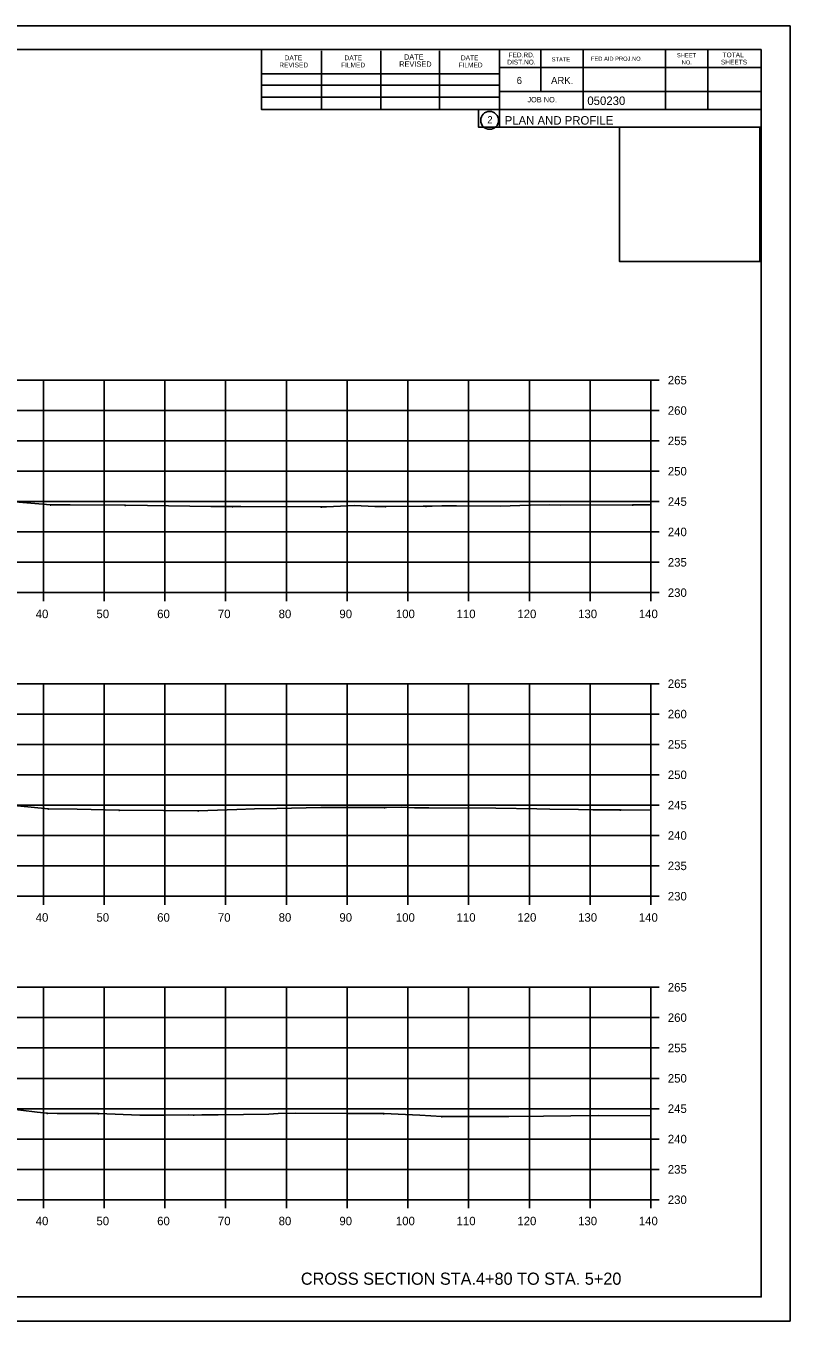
# Model space of a CAD drawing. Extents: x 1300404 to 1323571, y 234004 to 252077.
# Drawn here: x 1315754.4 to 1315880.2, y 241701.8 to 241915.1 of the extents above; entities that cross this region are included whole.
import ezdxf

# ---------------------------------------------------------------- set-up
doc = ezdxf.new("R2010")
doc.units = 0
for name, color, linetype in [('Default', 7, 'Continuous'), ('R_Axis', 7, 'Continuous'), ('R_Axis Annot', 7, 'Continuous'), ('R_Border', 7, 'Continuous'), ('R_Border Prem', 7, 'Continuous'), ('R_Draft', 7, 'Continuous'), ('R_Exist Surface', 7, 'Continuous'), ('R_Grid', 7, 'Continuous'), ('R_No Plot', 7, 'Continuous')]:
    doc.layers.add(name, color=color, linetype=linetype)

msp = doc.modelspace()

# ---------------------------------------------------------------- linework, layer by layer
at = {"layer": 'Default'}
for p, q in [((1315559.28, 241911.23), (1315875.46, 241911.23)), ((1315793.2, 241901.35), (1315793.2, 241911.23)), ((1315803.06, 241901.35), (1315803.06, 241911.03)), ((1315812.82, 241901.35), (1315812.82, 241911.03)), ((1315822.5, 241901.35), (1315822.5, 241911.03)), ((1315832.36, 241911.23), (1315832.36, 241898.43)), ((1315839.2, 241911.23), (1315839.2, 241904.29)), ((1315846.14, 241911.23), (1315846.14, 241901.35)), ((1315859.72, 241911.23), (1315859.72, 241901.35)), ((1315866.66, 241911.23), (1315866.66, 241901.35)), ((1315875.46, 241705.77), (1315875.46, 241911.23)), ((1315875.46, 241908.29), (1315832.36, 241908.29)), ((1315875.46, 241908.31), (1315875.46, 241908.31)), ((1315793.2, 241907.21), (1315832.36, 241907.21)), ((1315793.2, 241905.35), (1315832.36, 241905.35)), ((1315875.46, 241904.29), (1315832.36, 241904.29)), ((1315835.32, 241904.29), (1315875.46, 241904.29)), ((1315793.2, 241901.35), (1315793.2, 241903.41)), ((1315793.2, 241903.41), (1315832.36, 241903.41)), ((1315875.46, 241901.35), (1315793.2, 241901.35)), ((1315832.36, 241898.43), (1315875.46, 241898.43)), ((1315875.46, 241705.77), (1315559.28, 241705.77))]:
    msp.add_line(p, q, dxfattribs=at)
msp.add_circle((1315830.74, 241899.56), 1.47, dxfattribs=at)
at = {"layer": 'R_Axis'}
for p, q in [((1315857.28, 241821.77), (1315857.28, 241856.77)), ((1315858.68, 241856.77), (1315857.28, 241856.77)), ((1315858.68, 241851.77), (1315857.28, 241851.77)), ((1315858.68, 241846.77), (1315857.28, 241846.77)), ((1315858.68, 241841.77), (1315857.28, 241841.77)), ((1315858.68, 241836.77), (1315857.28, 241836.77)), ((1315858.68, 241831.77), (1315857.28, 241831.77)), ((1315858.68, 241826.77), (1315857.28, 241826.77)), ((1315577.28, 241821.77), (1315857.28, 241821.77)), ((1315757.28, 241820.37), (1315757.28, 241821.77)), ((1315767.28, 241820.37), (1315767.28, 241821.77)), ((1315777.28, 241820.37), (1315777.28, 241821.77)), ((1315787.28, 241820.37), (1315787.28, 241821.77)), ((1315797.28, 241820.37), (1315797.28, 241821.77)), ((1315807.28, 241820.37), (1315807.28, 241821.77)), ((1315817.28, 241820.37), (1315817.28, 241821.77)), ((1315827.28, 241820.37), (1315827.28, 241821.77)), ((1315837.28, 241820.37), (1315837.28, 241821.77)), ((1315847.28, 241820.37), (1315847.28, 241821.77)), ((1315857.28, 241820.37), (1315857.28, 241821.77)), ((1315858.68, 241821.77), (1315857.28, 241821.77)), ((1315857.28, 241771.77), (1315857.28, 241806.77)), ((1315858.68, 241806.77), (1315857.28, 241806.77)), ((1315858.68, 241801.77), (1315857.28, 241801.77)), ((1315858.68, 241796.77), (1315857.28, 241796.77)), ((1315858.68, 241791.77), (1315857.28, 241791.77)), ((1315858.68, 241786.77), (1315857.28, 241786.77)), ((1315858.68, 241781.77), (1315857.28, 241781.77)), ((1315858.68, 241776.77), (1315857.28, 241776.77)), ((1315577.28, 241771.77), (1315857.28, 241771.77)), ((1315757.28, 241770.37), (1315757.28, 241771.77)), ((1315767.28, 241770.37), (1315767.28, 241771.77)), ((1315777.28, 241770.37), (1315777.28, 241771.77)), ((1315787.28, 241770.37), (1315787.28, 241771.77)), ((1315797.28, 241770.37), (1315797.28, 241771.77)), ((1315807.28, 241770.37), (1315807.28, 241771.77)), ((1315817.28, 241770.37), (1315817.28, 241771.77)), ((1315827.28, 241770.37), (1315827.28, 241771.77)), ((1315837.28, 241770.37), (1315837.28, 241771.77)), ((1315847.28, 241770.37), (1315847.28, 241771.77)), ((1315857.28, 241770.37), (1315857.28, 241771.77)), ((1315858.68, 241771.77), (1315857.28, 241771.77)), ((1315857.28, 241721.77), (1315857.28, 241756.77)), ((1315858.68, 241756.77), (1315857.28, 241756.77)), ((1315858.68, 241751.77), (1315857.28, 241751.77)), ((1315858.68, 241746.77), (1315857.28, 241746.77)), ((1315858.68, 241741.77), (1315857.28, 241741.77)), ((1315858.68, 241736.77), (1315857.28, 241736.77)), ((1315858.68, 241731.77), (1315857.28, 241731.77)), ((1315858.68, 241726.77), (1315857.28, 241726.77)), ((1315577.28, 241721.77), (1315857.28, 241721.77)), ((1315757.28, 241720.37), (1315757.28, 241721.77)), ((1315767.28, 241720.37), (1315767.28, 241721.77)), ((1315777.28, 241720.37), (1315777.28, 241721.77)), ((1315787.28, 241720.37), (1315787.28, 241721.77)), ((1315797.28, 241720.37), (1315797.28, 241721.77)), ((1315807.28, 241720.37), (1315807.28, 241721.77)), ((1315817.28, 241720.37), (1315817.28, 241721.77)), ((1315827.28, 241720.37), (1315827.28, 241721.77)), ((1315837.28, 241720.37), (1315837.28, 241721.77)), ((1315847.28, 241720.37), (1315847.28, 241721.77)), ((1315857.28, 241720.37), (1315857.28, 241721.77)), ((1315858.68, 241721.77), (1315857.28, 241721.77))]:
    msp.add_line(p, q, dxfattribs=at)
at = {"layer": 'R_Draft'}
for points in [[(1315758.47, 241836.3), (1315758.52, 241836.2), (1315758.42, 241836.2)], [(1315770.75, 241836.22), (1315770.8, 241836.12), (1315770.7, 241836.12)], [(1315788.41, 241836), (1315788.46, 241835.9), (1315788.36, 241835.9)], [(1315803.05, 241835.94), (1315803.1, 241835.84), (1315803, 241835.84)], [(1315813.63, 241836.01), (1315813.68, 241835.91), (1315813.58, 241835.91)], [(1315820.28, 241836.05), (1315820.33, 241835.95), (1315820.23, 241835.95)], [(1315837.35, 241836.21), (1315837.4, 241836.11), (1315837.3, 241836.11)], [(1315854.29, 241836.27), (1315854.34, 241836.17), (1315854.24, 241836.17)], [(1315758.08, 241786.22), (1315758.13, 241786.12), (1315758.03, 241786.12)], [(1315813.44, 241786.45), (1315813.49, 241786.35), (1315813.39, 241786.35)], [(1315769.75, 241786.01), (1315769.8, 241785.91), (1315769.7, 241785.91)], [(1315782.76, 241785.89), (1315782.81, 241785.79), (1315782.71, 241785.79)], [(1315852.28, 241786.03), (1315852.33, 241785.93), (1315852.23, 241785.93)], [(1315757.91, 241736.06), (1315757.96, 241735.96), (1315757.86, 241735.96)], [(1315766.34, 241736.01), (1315766.39, 241735.91), (1315766.29, 241735.91)], [(1315782.03, 241735.78), (1315782.08, 241735.68), (1315781.98, 241735.68)], [(1315813.32, 241736.02), (1315813.37, 241735.92), (1315813.27, 241735.92)], [(1315822.87, 241735.52), (1315822.92, 241735.42), (1315822.82, 241735.42)], [(1315833.85, 241735.56), (1315833.9, 241735.46), (1315833.8, 241735.46)]]:
    msp.add_lwpolyline(points, close=True, dxfattribs=at)
at = {"layer": 'R_Exist Surface'}
for points in [[(1315748.62, 241837.08), (1315756.55, 241836.38), (1315758.47, 241836.25), (1315759.64, 241836.25), (1315761.67, 241836.21), (1315770.75, 241836.17), (1315774.43, 241836.14), (1315784.82, 241835.98), (1315788.41, 241835.95), (1315789.78, 241835.96), (1315803.05, 241835.89), (1315803.46, 241835.89), (1315803.87, 241835.91), (1315808.52, 241836.1), (1315811.87, 241835.95), (1315813.63, 241835.96), (1315819.81, 241836), (1315820.28, 241836), (1315821.3, 241836.01), (1315822.85, 241836.06), (1315824.2, 241836.06), (1315824.34, 241836.07), (1315825.3, 241836.05), (1315832.5, 241835.99), (1315837.35, 241836.16), (1315840.52, 241836.22), (1315842.46, 241836.16), (1315854.29, 241836.22), (1315857.1, 241836.25), (1315857.28, 241836.24)], [(1315750.74, 241786.89), (1315758.08, 241786.17), (1315762.86, 241786.11), (1315769.75, 241785.96), (1315777.03, 241785.91), (1315782.76, 241785.84), (1315789.12, 241786.07), (1315792.06, 241786.16), (1315795.71, 241786.2), (1315802.93, 241786.36), (1315813.44, 241786.4), (1315813.79, 241786.39), (1315816.18, 241786.41), (1315818.35, 241786.35), (1315820.76, 241786.32), (1315831.76, 241786.26), (1315838.51, 241786.17), (1315840.67, 241786.13), (1315845.4, 241786.06), (1315847.75, 241786.02), (1315852.28, 241785.98), (1315857.28, 241785.94)], [(1315748.12, 241737.18), (1315756.27, 241736.19), (1315757.91, 241736.01), (1315759.53, 241735.97), (1315766.34, 241735.96), (1315773.16, 241735.73), (1315777.19, 241735.71), (1315781.09, 241735.75), (1315782.03, 241735.73), (1315783.37, 241735.78), (1315786.03, 241735.75), (1315794.41, 241735.88), (1315795.95, 241735.98), (1315798.8, 241736.03), (1315807.46, 241735.97), (1315813.32, 241735.97), (1315819.24, 241735.71), (1315822.87, 241735.47), (1315823.16, 241735.47), (1315833.85, 241735.51), (1315839.63, 241735.56), (1315848.6, 241735.63), (1315857.28, 241735.6)]]:
    msp.add_lwpolyline(points, dxfattribs=at)
at = {"layer": 'R_Grid'}
for p, q in [((1315577.28, 241856.77), (1315857.28, 241856.77)), ((1315757.28, 241821.77), (1315757.28, 241856.77)), ((1315767.28, 241821.77), (1315767.28, 241856.77)), ((1315777.28, 241821.77), (1315777.28, 241856.77)), ((1315787.28, 241821.77), (1315787.28, 241856.77)), ((1315797.28, 241821.77), (1315797.28, 241856.77)), ((1315807.28, 241821.77), (1315807.28, 241856.77)), ((1315817.28, 241821.77), (1315817.28, 241856.77)), ((1315827.28, 241821.77), (1315827.28, 241856.77)), ((1315837.28, 241821.77), (1315837.28, 241856.77)), ((1315847.28, 241821.77), (1315847.28, 241856.77)), ((1315857.28, 241821.77), (1315857.28, 241856.77)), ((1315577.28, 241851.77), (1315857.28, 241851.77)), ((1315577.28, 241846.77), (1315857.28, 241846.77)), ((1315577.28, 241841.77), (1315857.28, 241841.77)), ((1315577.28, 241836.77), (1315857.28, 241836.77)), ((1315577.28, 241831.77), (1315857.28, 241831.77)), ((1315577.28, 241826.77), (1315857.28, 241826.77)), ((1315577.28, 241821.77), (1315857.28, 241821.77)), ((1315577.28, 241806.77), (1315857.28, 241806.77)), ((1315757.28, 241771.77), (1315757.28, 241806.77)), ((1315767.28, 241771.77), (1315767.28, 241806.77)), ((1315777.28, 241771.77), (1315777.28, 241806.77)), ((1315787.28, 241771.77), (1315787.28, 241806.77)), ((1315797.28, 241771.77), (1315797.28, 241806.77)), ((1315807.28, 241771.77), (1315807.28, 241806.77)), ((1315817.28, 241771.77), (1315817.28, 241806.77)), ((1315827.28, 241771.77), (1315827.28, 241806.77)), ((1315837.28, 241771.77), (1315837.28, 241806.77)), ((1315847.28, 241771.77), (1315847.28, 241806.77)), ((1315857.28, 241771.77), (1315857.28, 241806.77)), ((1315577.28, 241801.77), (1315857.28, 241801.77)), ((1315577.28, 241796.77), (1315857.28, 241796.77)), ((1315577.28, 241791.77), (1315857.28, 241791.77)), ((1315577.28, 241786.77), (1315857.28, 241786.77)), ((1315577.28, 241781.77), (1315857.28, 241781.77)), ((1315577.28, 241776.77), (1315857.28, 241776.77)), ((1315577.28, 241771.77), (1315857.28, 241771.77)), ((1315577.28, 241756.77), (1315857.28, 241756.77)), ((1315757.28, 241721.77), (1315757.28, 241756.77)), ((1315767.28, 241721.77), (1315767.28, 241756.77)), ((1315777.28, 241721.77), (1315777.28, 241756.77)), ((1315787.28, 241721.77), (1315787.28, 241756.77)), ((1315797.28, 241721.77), (1315797.28, 241756.77)), ((1315807.28, 241721.77), (1315807.28, 241756.77)), ((1315817.28, 241721.77), (1315817.28, 241756.77)), ((1315827.28, 241721.77), (1315827.28, 241756.77)), ((1315837.28, 241721.77), (1315837.28, 241756.77)), ((1315847.28, 241721.77), (1315847.28, 241756.77)), ((1315857.28, 241721.77), (1315857.28, 241756.77)), ((1315577.28, 241751.77), (1315857.28, 241751.77)), ((1315577.28, 241746.77), (1315857.28, 241746.77)), ((1315577.28, 241741.77), (1315857.28, 241741.77)), ((1315577.28, 241736.77), (1315857.28, 241736.77)), ((1315577.28, 241731.77), (1315857.28, 241731.77)), ((1315577.28, 241726.77), (1315857.28, 241726.77)), ((1315577.28, 241721.77), (1315857.28, 241721.77))]:
    msp.add_line(p, q, dxfattribs=at)
at = {"layer": 'R_No Plot'}
for p, q in [((1315546.87, 241915.12), (1315880.21, 241915.12)), ((1315546.87, 241701.79), (1315880.21, 241701.79))]:
    msp.add_line(p, q, dxfattribs=at)
for points in [[(1315546.87, 241915.12), (1315880.21, 241915.12), (1315880.21, 241701.78), (1315546.87, 241701.78)], [(1315793.2, 241911.23), (1315793.2, 241901.35), (1315828.93, 241901.35), (1315828.93, 241898.43), (1315852.13, 241898.43), (1315852.13, 241876.31), (1315875.46, 241876.31), (1315875.46, 241705.77), (1315559.28, 241705.77), (1315559.28, 241911.23)], [(1315852.13, 241898.46), (1315875.23, 241898.46), (1315875.23, 241876.31), (1315852.13, 241876.31)]]:
    msp.add_lwpolyline(points, close=True, dxfattribs=at)

# ---------------------------------------------------------------- texts
at = {"layer": 'Default'}
msp.add_text('2', height=1.17, dxfattribs=at).set_placement((1315830.36, 241899.08))
at = {"layer": 'R_Axis Annot'}
for s, p in [('265', (1315860.08, 241856.07)), ('260', (1315860.08, 241851.07)), ('255', (1315860.08, 241846.07)), ('250', (1315860.08, 241841.07)), ('245', (1315860.08, 241836.07)), ('240', (1315860.08, 241831.07)), ('235', (1315860.08, 241826.07)), ('230', (1315860.08, 241821.07)), ('40', (1315756.01, 241817.57)), ('50', (1315766.01, 241817.57)), ('60', (1315776.01, 241817.57)), ('70', (1315786.01, 241817.57)), ('80', (1315796.01, 241817.57)), ('90', (1315806.01, 241817.57)), ('100', (1315815.31, 241817.57)), ('110', (1315825.31, 241817.57)), ('120', (1315835.31, 241817.57)), ('130', (1315845.31, 241817.57)), ('140', (1315855.31, 241817.57)), ('265', (1315860.08, 241806.07)), ('260', (1315860.08, 241801.07)), ('255', (1315860.08, 241796.07)), ('250', (1315860.08, 241791.07)), ('245', (1315860.08, 241786.07)), ('240', (1315860.08, 241781.07)), ('235', (1315860.08, 241776.07)), ('230', (1315860.08, 241771.07)), ('40', (1315756.01, 241767.57)), ('50', (1315766.01, 241767.57)), ('60', (1315776.01, 241767.57)), ('70', (1315786.01, 241767.57)), ('80', (1315796.01, 241767.57)), ('90', (1315806.01, 241767.57)), ('100', (1315815.31, 241767.57)), ('110', (1315825.31, 241767.57)), ('120', (1315835.31, 241767.57)), ('130', (1315845.31, 241767.57)), ('140', (1315855.31, 241767.57)), ('265', (1315860.08, 241756.07)), ('260', (1315860.08, 241751.07)), ('255', (1315860.08, 241746.07)), ('250', (1315860.08, 241741.07)), ('245', (1315860.08, 241736.07)), ('240', (1315860.08, 241731.07)), ('235', (1315860.08, 241726.07)), ('230', (1315860.08, 241721.07)), ('40', (1315756.01, 241717.57)), ('50', (1315766.01, 241717.57)), ('60', (1315776.01, 241717.57)), ('70', (1315786.01, 241717.57)), ('80', (1315796.01, 241717.57)), ('90', (1315806.01, 241717.57)), ('100', (1315815.31, 241717.57)), ('110', (1315825.31, 241717.57)), ('120', (1315835.31, 241717.57)), ('130', (1315845.31, 241717.57)), ('140', (1315855.31, 241717.57))]:
    msp.add_text(s, height=1.4, dxfattribs=at).set_placement(p)
at = {"layer": 'R_Border'}
for s, height, p in [('DATE', 0.782, (1315797, 241909.47)), ('DATE', 0.782, (1315806.86, 241909.47)), ('DATE', 0.879, (1315816.64, 241909.57)), ('DATE', 0.782, (1315826.02, 241909.47)), ('FED.RD.', 0.782, (1315833.84, 241909.95)), ('STATE', 0.684, (1315840.96, 241909.27)), ('FED.AID PROJ.NO.', 0.684, (1315847.42, 241909.37)), ('SHEET', 0.684, (1315861.58, 241909.95)), ('TOTAL', 0.782, (1315869.1, 241909.95)), ('REVISED', 0.782, (1315796.12, 241908.29)), ('FILMED', 0.782, (1315806.28, 241908.29)), ('REVISED', 0.879, (1315815.86, 241908.39)), ('FILMED', 0.782, (1315825.62, 241908.29)), ('DIST.NO.', 0.782, (1315833.64, 241908.77)), ('NO.', 0.684, (1315862.36, 241908.77)), ('SHEETS', 0.782, (1315868.82, 241908.77)), ('6', 1.17, (1315835.2, 241905.55)), ('ARK.', 1.172, (1315840.86, 241905.55)), ('JOB NO.', 0.879, (1315836.96, 241902.53))]:
    msp.add_text(s, height=height, dxfattribs=at).set_placement(p)
for s, p in [('050230', (1315846.83, 241902.09)), ('PLAN AND PROFILE', (1315833.22, 241898.86))]:
    msp.add_text(s, height=1.4, rotation=360, dxfattribs=at).set_placement(p)
at = {"layer": 'R_Border Prem'}
msp.add_text('DWB', height=0.01, dxfattribs=at).set_placement((1315836.15, 241892.74))
at = {"layer": 'R_Draft'}
msp.add_text('CROSS SECTION STA.4+80 TO STA. 5+20', height=2, dxfattribs=at).set_placement((1315799.67, 241707.77))

doc.saveas('drawing.dxf')
